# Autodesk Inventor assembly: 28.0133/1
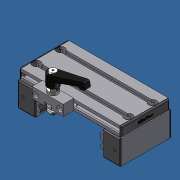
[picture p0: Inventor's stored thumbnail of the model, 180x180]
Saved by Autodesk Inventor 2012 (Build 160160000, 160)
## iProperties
Created: 2007-06
Part Number: 28.0133/1
Document SubType Name: Assembly
Designer: Andy Moles
Mass: 1009.56 g
Surface Area: 2358.71 cm^2
Volume: 366.363 cm^3
Density: 2.75563 g/cm^3
Description: SLIDE LWG 32X45-90 WITH TOP CLAMP
Author: Andy Moles
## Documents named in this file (3)
- C:\Andys Backup Data\ANDY'S INVENTOR\INVENTOR LIBRARIES\PARTS LIBRARY\READY FOR USE MODULES LG\28.0133_1 SLIDE LWG 32X45-90 WITH TOP CLAMP.iam
- C:\Andys Backup Data\ANDY'S INVENTOR\INVENTOR LIBRARIES\PARTS LIBRARY\COMPONENTS LR\28.0270_9 SLIDE CLAMPING UNIT 2mm OFFSET..iam
- C:\Andys Backup Data\ANDY'S INVENTOR\INVENTOR LIBRARIES\PARTS LIBRARY\READY FOR USE MODULES LG\28.0133 SLIDE LWG 32X45-90.iam
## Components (2 placed, 2 different names)
1. 28.0270_9 SLIDE CLAMPING UNIT 2mm OFFSET.:1 [sub-assembly] — Mate:1, Mate:2, Mate:3
2. 28.0133 SLIDE LWG 32X45-90:1 [sub-assembly] — Mate:1, Mate:2, Mate:3
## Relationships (3: Mate 3)
- Mate:1: 28.0270_9 SLIDE CLAMPING UNIT 2mm OFFSET.:1 ↔ 28.0133 SLIDE LWG 32X45-90:1
- Mate:2: 28.0270_9 SLIDE CLAMPING UNIT 2mm OFFSET.:1 ↔ 28.0133 SLIDE LWG 32X45-90:1
- Mate:3: 28.0270_9 SLIDE CLAMPING UNIT 2mm OFFSET.:1 ↔ 28.0133 SLIDE LWG 32X45-90:1
